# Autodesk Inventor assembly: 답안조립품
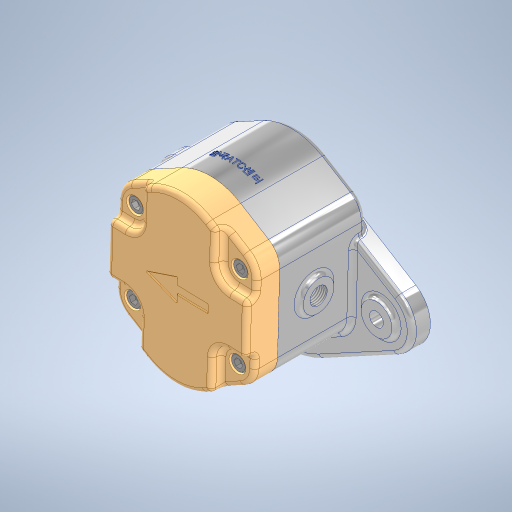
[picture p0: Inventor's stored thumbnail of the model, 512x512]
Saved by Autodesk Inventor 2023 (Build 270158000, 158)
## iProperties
Created: 2025-11
Part Number: 답안조립품
Document SubType Name: Assembly
Designer: home
Author: home
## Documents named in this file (11)
- C:\Users\home\Desktop\751103V1012\답안조립품.iam
- C:\Users\home\Desktop\751103V1012\커버.ipt
- C:\Users\home\Desktop\751103V1012\3자 실링.ipt
- C:\Users\home\Desktop\751103V1012\6각 구멍붙이 볼트 M6x16.ipt
- C:\Users\home\Desktop\751103V1012\DU 부시.ipt
- C:\Users\home\Desktop\751103V1012\가이드 블록.ipt
- C:\Users\home\Desktop\751103V1012\구동기어.ipt
- C:\Users\home\Desktop\751103V1012\스퍼기어.ipt
- C:\Users\home\Desktop\751103V1012\실링.ipt
- C:\Users\home\Desktop\751103V1012\오일 실 16 30 7.ipt
- C:\Users\home\Desktop\751103V1012\본체.ipt
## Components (11 placed, 5 different names)
1. 3자 실링:1
2. 6각 구멍붙이 볼트 M6x16:1
3. DU 부시:1
4. 가이드 블록:1
5. 구동기어:1
6. DU 부시:2
7. DU 부시:3
8. DU 부시:4
9. 6각 구멍붙이 볼트 M6x16:2
10. 6각 구멍붙이 볼트 M6x16:3
11. 6각 구멍붙이 볼트 M6x16:4
